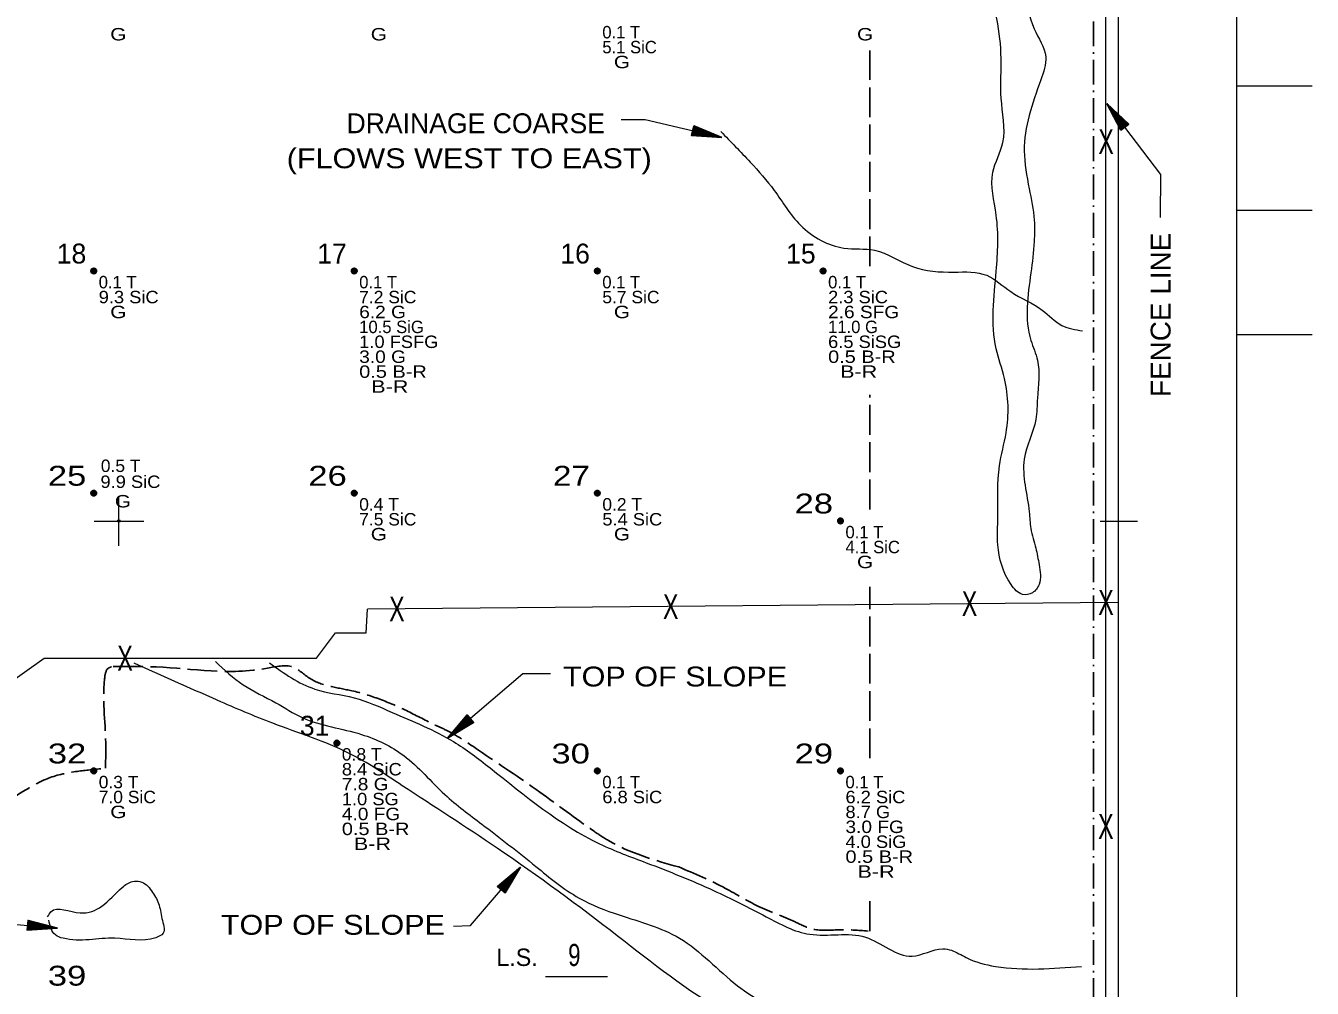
# Model space of a CAD drawing. Extents: x -496 to 480, y -450 to 700.
# Drawn here: x -38 to 480, y -188 to 199 of the extents above; entities that cross this region are included whole.
import ezdxf
from ezdxf.enums import TextEntityAlignment as Align

# ---------------------------------------------------------------- set-up
doc = ezdxf.new("R2010")
doc.units = 0
doc.header["$LTSCALE"] = 2
doc.header["$PDMODE"] = 32
doc.header["$PDSIZE"] = 1
doc.linetypes.add('DOT_DASHED', pattern=[7.7, 5, -1.2, 0.3, -1.2])
doc.linetypes.add('LONG_DASHED', pattern=[7.5, 6, -1.5])
for name, color, linetype, lineweight in [('1', 7, 'Continuous', 13), ('2', 7, 'Continuous', 35), ('3', 7, 'Continuous', 13), ('4', 7, 'Continuous', 25)]:
    doc.layers.add(name, color=color, linetype=linetype, lineweight=lineweight)

msp = doc.modelspace()

# ---------------------------------------------------------------- linework, layer by layer
at = {"layer": '1'}
for p, q in [((402.281, -245.555), (402.281, 402.339)), ((480.331, 174.973), (449.983, 174.973)), ((480.331, 124.973), (449.983, 124.973)), ((480.331, 74.973), (449.983, 74.973)), ((-0.017, -10.027), (-0.017, 9.973)), ((-10.017, -0.027), (9.983, -0.027)), ((394.983, -0.027), (409.983, -0.027)), ((171.67, -183.226), (196.67, -183.226))]:
    msp.add_line(p, q, dxfattribs=at)
msp.add_lwpolyline([(449.983, -450.027), (449.983, 399.973), (449.983, 699.973), (-450.017, 699.973), (-450.017, 49.973), (-450.017, -450.027)], dxfattribs=at)
for p in [(0, 0), (0.001, -0.011)]:
    msp.add_point(p, dxfattribs=at)
at = {"layer": '2', "linetype": 'LONG_DASHED', "lineweight": 25}
for p, q in [((302.281, 102.482), (302.281, 189.292)), ((302.281, 4.688), (302.281, 50.791)), ((302.281, -95.435), (302.281, -26.514)), ((302.281, -164.988), (302.281, -152.715))]:
    msp.add_line(p, q, dxfattribs=at)
at = {"layer": '2'}
for centre in [(-10.129, 100.614), (94.721, 100.614), (192.581, 100.614), (283.451, 100.614), (-10.129, 11.214), (94.721, 11.214), (192.581, 11.214), (290.441, 0.039), (87.731, -89.361), (-10.129, -100.536), (192.581, -100.536), (290.441, -100.536)]:
    msp.add_circle(centre, 1, dxfattribs=at)
for points in [[(-10.14, 101.501), (-9.409, 101.097), (-9.258, 100.248), (-9.943, 99.72), (-10.752, 99.951), (-11.038, 100.709), (-10.791, 101.271), (-10.218, 101.439), (-9.544, 100.945), (-9.561, 100.203), (-10.078, 99.945), (-10.6, 100.114), (-10.825, 100.76), (-10.241, 101.226), (-9.803, 100.692), (-9.842, 100.209), (-10.471, 100.344), (-10.325, 100.979), (-10.033, 100.428)], [(94.71, 101.501), (95.441, 101.097), (95.592, 100.248), (94.907, 99.72), (94.098, 99.951), (93.812, 100.709), (94.059, 101.271), (94.632, 101.439), (95.306, 100.945), (95.289, 100.203), (94.772, 99.945), (94.25, 100.114), (94.025, 100.76), (94.609, 101.226), (95.047, 100.692), (95.008, 100.209), (94.379, 100.344), (94.525, 100.979), (94.817, 100.428)], [(192.57, 101.501), (193.301, 101.097), (193.452, 100.248), (192.767, 99.72), (191.958, 99.951), (191.672, 100.709), (191.919, 101.271), (192.492, 101.439), (193.166, 100.945), (193.149, 100.203), (192.632, 99.945), (192.11, 100.114), (191.885, 100.76), (192.469, 101.226), (192.907, 100.692), (192.868, 100.209), (192.239, 100.344), (192.385, 100.979), (192.677, 100.428)], [(283.44, 101.501), (284.171, 101.097), (284.322, 100.248), (283.637, 99.72), (282.828, 99.951), (282.542, 100.709), (282.789, 101.271), (283.362, 101.439), (284.036, 100.945), (284.019, 100.203), (283.502, 99.945), (282.98, 100.114), (282.755, 100.76), (283.339, 101.226), (283.777, 100.692), (283.738, 100.209), (283.109, 100.344), (283.255, 100.979), (283.547, 100.428)], [(-10.14, 12.101), (-9.409, 11.697), (-9.258, 10.848), (-9.943, 10.32), (-10.752, 10.551), (-11.038, 11.309), (-10.791, 11.871), (-10.218, 12.039), (-9.544, 11.545), (-9.561, 10.803), (-10.078, 10.545), (-10.6, 10.714), (-10.825, 11.36), (-10.241, 11.826), (-9.803, 11.292), (-9.842, 10.809), (-10.471, 10.944), (-10.325, 11.579), (-10.033, 11.028)], [(94.71, 12.101), (95.441, 11.697), (95.592, 10.848), (94.907, 10.32), (94.098, 10.551), (93.812, 11.309), (94.059, 11.871), (94.632, 12.039), (95.306, 11.545), (95.289, 10.803), (94.772, 10.545), (94.25, 10.714), (94.025, 11.36), (94.609, 11.826), (95.047, 11.292), (95.008, 10.809), (94.379, 10.944), (94.525, 11.579), (94.817, 11.028)], [(192.57, 12.101), (193.301, 11.697), (193.452, 10.848), (192.767, 10.32), (191.958, 10.551), (191.672, 11.309), (191.919, 11.871), (192.492, 12.039), (193.166, 11.545), (193.149, 10.803), (192.632, 10.545), (192.11, 10.714), (191.885, 11.36), (192.469, 11.826), (192.907, 11.292), (192.868, 10.809), (192.239, 10.944), (192.385, 11.579), (192.677, 11.028)], [(290.43, 0.926), (291.161, 0.522), (291.312, -0.327), (290.627, -0.855), (289.818, -0.624), (289.532, 0.134), (289.779, 0.696), (290.352, 0.864), (291.026, 0.37), (291.009, -0.372), (290.492, -0.63), (289.97, -0.461), (289.745, 0.185), (290.329, 0.651), (290.767, 0.117), (290.728, -0.366), (290.099, -0.231), (290.245, 0.404), (290.537, -0.147)], [(87.72, -88.474), (88.451, -88.878), (88.602, -89.727), (87.917, -90.255), (87.108, -90.024), (86.822, -89.266), (87.069, -88.704), (87.642, -88.536), (88.316, -89.03), (88.299, -89.772), (87.782, -90.03), (87.26, -89.861), (87.035, -89.215), (87.619, -88.749), (88.057, -89.283), (88.018, -89.766), (87.389, -89.631), (87.535, -88.996), (87.827, -89.547)], [(-10.14, -99.649), (-9.409, -100.053), (-9.258, -100.902), (-9.943, -101.43), (-10.752, -101.199), (-11.038, -100.441), (-10.791, -99.879), (-10.218, -99.711), (-9.544, -100.205), (-9.561, -100.947), (-10.078, -101.205), (-10.6, -101.036), (-10.825, -100.39), (-10.241, -99.924), (-9.803, -100.458), (-9.842, -100.941), (-10.471, -100.806), (-10.325, -100.171), (-10.033, -100.722)], [(192.57, -99.649), (193.301, -100.053), (193.452, -100.902), (192.767, -101.43), (191.958, -101.199), (191.672, -100.441), (191.919, -99.879), (192.492, -99.711), (193.166, -100.205), (193.149, -100.947), (192.632, -101.205), (192.11, -101.036), (191.885, -100.39), (192.469, -99.924), (192.907, -100.458), (192.868, -100.941), (192.239, -100.806), (192.385, -100.171), (192.677, -100.722)], [(290.43, -99.649), (291.161, -100.053), (291.312, -100.902), (290.627, -101.43), (289.818, -101.199), (289.532, -100.441), (289.779, -99.879), (290.352, -99.711), (291.026, -100.205), (291.009, -100.947), (290.492, -101.205), (289.97, -101.036), (289.745, -100.39), (290.329, -99.924), (290.767, -100.458), (290.728, -100.941), (290.099, -100.806), (290.245, -100.171), (290.537, -100.722)]]:
    msp.add_spline(points, degree=3, dxfattribs=at)
at = {"layer": '2', "linetype": 'LONG_DASHED', "lineweight": 25}
for points in [[(-5.46, -99.466), (-5.252, -90.93), (-5.748, -63.446), (-4.261, -59.237), (-2.343, -58.49)], [(-2.343, -58.49), (15.058, -58.715), (59.763, -59.234), (69.9, -58.715), (76.917, -63.388), (84.974, -66.503), (93.811, -68.32), (104.987, -71.695), (116.424, -76.628), (127.34, -82.08), (132.278, -84.416), (144.754, -92.204), (169.445, -109.079), (191.018, -124.655), (196.996, -128.55), (225.326, -139.194)], [(-46.213, -113.44), (-37.202, -108.011), (-28.328, -103.466), (-16.725, -100.739), (-6.714, -99.603), (-5.46, -99.466)], [(225.326, -139.194), (244.199, -147.831), (257.196, -154.935), (272.155, -161.303), (279.512, -164.243), (289.566, -164.488), (301.582, -164.977)]]:
    msp.add_spline(points, degree=3, dxfattribs=at)
at = {"layer": '3'}
for p, q in [((397.281, -246.457), (397.281, 397.339)), ((402.135, -32.826), (100.033, -35.45))]:
    msp.add_line(p, q, dxfattribs=at)
at = {"layer": '3', "linetype": 'DOT_DASHED', "lineweight": 25}
msp.add_line((392.281, 385.802), (392.281, -246.006), dxfattribs=at)
at = {"layer": '3'}
msp.add_lwpolyline([(-418.392, 11.933), (-163.468, 10.85), (-155.332, 0.015), (-122.789, -0.527), (-81.567, -55.245), (-66.922, -55.787), (-66.922, -66.622), (-46.854, -67.164), (-30.04, -55.245), (79.523, -55.245), (87.202, -45.019), (99.497, -44.943), (100.033, -35.45)], dxfattribs=at)
for points in [[(-407.583, 368.504), (-377.691, 369.409), (-355.045, 369.409), (-344.175, 368.504), (-328.776, 371.218), (-313.377, 372.123), (-278.956, 368.504), (-253.593, 366.695), (-220.983, 368.504), (-195.62, 369.409), (-113.189, 371.218), (-62.463, 366.695), (-15.36, 370.314), (129.573, 369.409), (163.088, 366.695), (215.626, 369.409), (283.563, 369.409), (313.456, 370.314), (344.254, 369.409), (357.841, 369.409), (358.747, 364.885), (359.653, 358.552), (346.971, 354.028), (317.985, 355.837), (282.658, 358.552), (167.617, 358.552), (86.999, 357.647), (29.026, 354.028), (-29.853, 357.647), (-94.167, 358.552), (-118.624, 356.742), (-177.503, 359.456), (-248.158, 354.932), (-325.153, 358.552), (-355.951, 354.932), (-383.126, 358.552), (-389.467, 354.932), (-393.996, 342.265), (-393.09, 244.549), (-392.184, 178.5), (-393.996, 113.356), (-393.996, 88.927), (-393.09, 59.974), (-392.184, 33.736), (-397.619, 15.64), (-404.866, 15.64), (-411.207, 31.021), (-407.583, 90.737), (-410.301, 145.024), (-408.489, 188.453), (-408.489, 262.645), (-411.207, 278.931), (-407.583, 312.408), (-409.395, 347.694), (-409.395, 353.123), (-415.736, 357.647)], [(353.782, 336.707), (359.096, 341.351), (366.402, 339.361), (369.059, 331.4), (366.402, 320.121), (367.731, 310.833), (365.738, 297.564), (366.402, 288.94), (367.066, 284.296), (367.066, 273.017), (369.059, 262.402), (369.059, 251.787), (367.066, 239.846), (364.41, 233.875), (364.41, 227.904), (368.395, 198.049), (373.044, 186.771), (371.052, 177.483), (364.41, 148.955), (366.402, 133.696), (368.395, 121.091), (368.395, 112.466), (367.066, 99.861), (367.066, 72.66), (369.723, 64.699), (369.723, 49.44), (369.059, 40.815), (364.41, 24.893), (366.402, 3.663), (367.066, -2.971), (369.059, -10.932), (370.387, -17.567), (370.387, -25.528), (367.731, -28.845), (363.745, -29.509), (359.096, -25.528), (353.782, -9.606), (353.782, 1.673), (354.447, 22.239), (357.103, 35.508), (356.439, 57.401), (353.118, 69.343), (353.118, 100.524), (353.118, 123.081), (351.79, 140.331), (355.775, 152.272), (355.111, 170.185), (355.111, 184.117), (353.782, 200.04), (350.461, 221.933), (353.118, 238.519), (355.775, 253.114), (355.111, 274.344), (353.118, 294.247), (351.125, 313.487), (350.461, 322.775), (351.79, 332.063), (354.447, 338.697)], [(242.275, 156.692), (254.119, 144.424), (263.769, 133.033), (274.297, 119.012), (282.631, 112.878), (291.842, 109.811), (304.125, 108.935), (319.477, 102.363), (336.146, 100.172), (349.305, 98.858), (358.955, 92.286), (371.676, 84.837), (379.572, 78.703), (387.906, 76.513)], [(38.939, -56.557), (49.996, -65.901), (63.179, -73.122), (73.81, -79.069), (97.624, -85.865), (114.634, -94.36), (131.219, -110.076), (146.103, -121.97), (167.791, -138.96), (185.226, -151.703), (201.386, -158.499), (225.625, -167.844), (249.014, -186.958), (260.496, -194.604), (267.3, -199.276), (275.38, -208.196), (281.758, -211.169), (291.16, -212.829)], [(237.229, -257.097), (233.19, -252.437), (217.369, -252.437), (203.408, -246.859), (199.685, -239.422), (195.963, -231.985), (201.547, -229.197), (211.784, -235.704), (240.636, -237.563), (254.596, -236.633), (262.042, -230.126), (263.903, -214.323), (245.289, -198.519), (200.616, -166.912), (152.22, -131.587), (114.062, -106.488), (92.656, -93.473), (61.943, -81.388), (39.607, -72.092), (6.102, -57.218)], [(60.597, -57.041), (78.822, -67.611), (94.695, -71.134), (109.98, -77.006), (134.671, -88.75), (149.368, -99.32), (193.46, -129.855), (212.273, -137.489), (239.315, -148.646), (260.479, -159.215), (278.116, -166.262), (300.456, -167.436), (309.862, -172.134), (319.268, -175.07), (331.614, -172.134), (335.141, -172.721), (341.02, -175.657), (352.778, -179.18), (387.464, -179.18)], [(-28.687, -159.22), (-27.354, -157.223), (-15.577, -157.667), (-6.912, -155.003), (1.309, -147.458), (5.531, -145.016), (11.086, -146.348), (13.086, -148.789), (15.974, -153.894), (17.308, -159.886), (17.752, -165.878), (14.863, -167.654), (-1.579, -167.876), (-22.465, -167.876), (-25.576, -166.544), (-28.242, -160.552)]]:
    msp.add_spline(points, degree=3, dxfattribs=at)
at = {"layer": '4', "lineweight": 13}
for points in [[(419.287, 122.176), (419.425, 139.363), (397.64, 168.053)], [(202.101, 161.518), (211.806, 161.518), (242.654, 154.248)], [(173.732, -61.419), (162.605, -61.419), (132.313, -87.353)], [(134.713, -163.058), (141.529, -162.775), (161.694, -139.229)], [(-80.976, -159.656), (-71.087, -159.656), (-24.776, -163.751)]]:
    msp.add_lwpolyline(points, dxfattribs=at)
at = {"layer": '4'}
for points in [[(397.64, 168.053), (403.304, 157.286), (406.49, 159.705)], [(242.654, 154.248), (231.433, 158.947), (230.515, 155.054)], [(132.313, -87.353), (142.73, -81.068), (140.128, -78.029)], [(161.694, -139.229), (152.369, -147.043), (155.407, -149.645)], [(-24.776, -163.751), (-36.554, -160.702), (-36.906, -164.686)]]:
    msp.add_lwpolyline(points, close=True, dxfattribs=at)
for points in [[(403.339, 157.436), (397.987, 167.595), (406.261, 159.735), (403.451, 157.576), (398.432, 167.008), (406.007, 159.787), (403.467, 157.803), (398.903, 166.389), (405.716, 159.81), (403.56, 158.037), (399.421, 165.672), (405.416, 159.882), (403.602, 158.342), (400.044, 164.812), (405.092, 159.88), (403.679, 158.67), (400.719, 163.889), (404.664, 159.907), (403.71, 159.02), (401.427, 162.85), (404.249, 160.025), (403.72, 159.435), (402.346, 161.674), (403.722, 160.114)], [(231.501, 158.809), (242.096, 154.38), (230.712, 155.176), (231.504, 158.63), (241.379, 154.549), (230.94, 155.298), (231.636, 158.444), (240.621, 154.728), (231.179, 155.466), (231.713, 158.205), (239.765, 154.951), (231.457, 155.6), (231.875, 157.943), (238.738, 155.217), (231.705, 155.808), (232.025, 157.641), (237.629, 155.5), (232.052, 156.06), (232.224, 157.352), (236.422, 155.851), (232.448, 156.233), (232.48, 157.025), (234.965, 156.173), (232.91, 156.5)], [(142.578, -81.041), (132.75, -86.98), (140.111, -78.26), (142.432, -80.938), (133.309, -86.501), (140.075, -78.516), (142.204, -80.935), (133.9, -85.995), (140.069, -78.808), (141.965, -80.856), (134.586, -85.435), (140.014, -79.111), (141.658, -80.832), (135.407, -84.763), (140.035, -79.435), (141.326, -80.775), (136.29, -84.035), (140.033, -79.863), (140.975, -80.764), (137.286, -83.268), (139.94, -80.285), (140.56, -80.778), (138.405, -82.282), (139.882, -80.816)], [(152.523, -147.045), (161.32, -139.665), (155.389, -149.414), (152.684, -147.125), (160.841, -140.224), (155.385, -149.155), (152.909, -147.093), (160.335, -140.815), (155.346, -148.866), (153.157, -147.134), (159.744, -141.474), (155.354, -148.558), (153.464, -147.111), (159.036, -142.264), (155.283, -148.241), (153.801, -147.116), (158.276, -143.12), (155.219, -147.818), (154.15, -147.072), (157.41, -144.031), (155.246, -147.387), (154.557, -146.995), (156.455, -145.178), (155.222, -146.853)], [(-36.466, -160.829), (-25.348, -163.7), (-36.729, -164.537), (-36.438, -161.006), (-26.082, -163.635), (-36.52, -164.384), (-36.281, -161.171), (-26.857, -163.567), (-36.308, -164.184), (-36.17, -161.397), (-27.736, -163.468), (-36.053, -164.011), (-35.972, -161.633), (-28.791, -163.351), (-35.836, -163.77), (-35.781, -161.91), (-29.929, -163.23), (-35.528, -163.472), (-35.543, -162.168), (-31.174, -163.055), (-35.162, -163.244), (-35.243, -162.455), (-32.661, -162.944), (-34.742, -162.913)]]:
    msp.add_lwpolyline(points, dxfattribs=at)

# ---------------------------------------------------------------- texts
at = {"layer": '1', "width": 0.75}
msp.add_text('9', height=8.89, dxfattribs=at).set_placement((183.312, -179.052), align=Align.CENTER)
at = {"layer": '1'}
msp.add_text('L.S.', height=7, dxfattribs=at).set_placement((160.254, -179.023), align=Align.CENTER)
at = {"layer": '2'}
for s, width, p in [('  G        ', 1.25, (-8.129, 193.364)), ('  G        ', 1.25, (96.721, 193.364)), ('  G        ', 1.25, (292.441, 193.364)), ('  G        ', 1.25, (194.581, 182.189)), ('9.3 SiC    ', 1.1, (-8.129, 87.614)), ('7.2 SiC    ', 1.05, (96.721, 87.614)), ('5.7 SiC    ', 1.05, (194.581, 87.614)), ('2.3 SiC    ', 1.1, (285.451, 87.614)), ('  G        ', 1.25, (-8.129, 81.614)), ('6.2 G      ', 1.15, (96.721, 81.614)), ('  G        ', 1.25, (194.581, 81.614)), ('2.6 SFG    ', 1.15, (285.451, 81.614)), ('1.0 FSFG   ', 1.1, (96.721, 69.614)), ('6.5 SiSG   ', 1.1, (285.451, 69.614)), ('3.0 G      ', 1.15, (96.721, 63.614)), ('0.5 B-R    ', 1.2, (285.451, 63.614)), ('0.5 B-R    ', 1.2, (96.721, 57.614)), ('  B-R      ', 1.3, (285.451, 57.614)), ('  B-R      ', 1.3, (96.721, 51.614)), ('0.5 T      ', 1.05, (-7.282, 19.724)), ('9.9 SiC    ', 1.1, (-7.423, 13.302)), ('  G        ', 1.25, (-6.294, 5.468)), ('0.4 T      ', 1.05, (96.721, 4.214)), ('0.2 T      ', 1.05, (194.581, 4.214)), ('7.5 SiC    ', 1.05, (96.721, -1.786)), ('5.4 SiC    ', 1.1, (194.581, -1.786)), ('  G        ', 1.25, (96.721, -7.786)), ('  G        ', 1.25, (194.581, -7.786)), ('  G        ', 1.25, (292.441, -18.961)), ('0.8 T      ', 1.05, (89.731, -96.361)), ('8.4 SiC    ', 1.1, (89.731, -102.361)), ('0.3 T      ', 1.05, (-8.129, -107.536)), ('7.8 G      ', 1.15, (89.731, -108.361)), ('7.0 SiC    ', 1.05, (-8.129, -113.536)), ('6.8 SiC    ', 1.1, (194.581, -113.536)), ('6.2 SiC    ', 1.1, (292.441, -113.536)), ('1.0 SG     ', 1.1, (89.731, -114.361)), ('  G        ', 1.25, (-8.129, -119.536)), ('4.0 FG     ', 1.15, (89.731, -120.361)), ('8.7 G      ', 1.1, (292.441, -119.536)), ('0.5 B-R    ', 1.2, (89.731, -126.361)), ('3.0 FG     ', 1.15, (292.441, -125.536)), ('  B-R      ', 1.3, (89.731, -132.361)), ('4.0 SiG    ', 1.1, (292.441, -131.536)), ('0.5 B-R    ', 1.2, (292.441, -137.536)), ('  B-R      ', 1.3, (292.441, -143.536))]:
    msp.add_text(s, height=5, dxfattribs=dict(at, width=width)).set_placement(p)
for s, p in [('0.1 T      ', (194.581, 194.189)), ('5.1 SiC    ', (194.581, 188.189)), ('0.1 T      ', (-8.129, 93.614)), ('0.1 T      ', (96.721, 93.614)), ('0.1 T      ', (194.581, 93.614)), ('0.1 T      ', (285.451, 93.614)), ('10.5 SiG   ', (96.721, 75.614)), ('11.0 G     ', (285.451, 75.614)), ('0.1 T      ', (292.441, -6.961)), ('4.1 SiC    ', (292.441, -12.961)), ('0.1 T      ', (194.581, -107.536)), ('0.1 T      ', (292.441, -107.536))]:
    msp.add_text(s, height=5, dxfattribs=at).set_placement(p)
for s, p in [(' 18', (-13.129, 103.614)), (' 17', (91.721, 103.614)), (' 16', (189.581, 103.614)), (' 15', (280.451, 103.614)), (' 31', (84.731, -86.361))]:
    msp.add_text(s, height=8, dxfattribs=at).set_placement(p, align=Align.RIGHT)
for s, width, p in [(' 25', 1.3, (-13.129, 14.214)), (' 26', 1.3, (91.721, 14.214)), (' 27', 1.25, (189.581, 14.214)), (' 28', 1.3, (287.441, 3.039)), (' 32', 1.3, (-13.129, -97.536)), (' 30', 1.3, (189.581, -97.536)), (' 29', 1.3, (287.441, -97.536)), (' 39', 1.3, (-13.129, -186.936))]:
    msp.add_text(s, height=8, dxfattribs=dict(at, width=width)).set_placement(p, align=Align.RIGHT)
at = {"layer": '3', "width": 0.7}
for p in [(397.338, 147.663), (111.893, -40.418), (222.099, -39.44), (342.378, -38.222), (397.293, -37.75), (2.475, -60.171), (397.253, -127.917)]:
    msp.add_text('X', height=10, dxfattribs=at).set_placement(p, align=Align.CENTER)
at = {"layer": '4'}
msp.add_text('DRAINAGE COARSE', height=8, dxfattribs=at).set_placement((143.628, 156.037), align=Align.CENTER)
at = {"layer": '4', "width": 1.15}
for s, p in [('(FLOWS WEST TO EAST)', (141.012, 141.946)), ('TOP OF SLOPE', (223.839, -66.567)), ('TOP OF SLOPE', (86.144, -166.471))]:
    msp.add_text(s, height=8, dxfattribs=at).set_placement(p, align=Align.CENTER)
at = {"layer": '4', "width": 1.05}
msp.add_text('FENCE LINE', height=8, rotation=90, dxfattribs=at).set_placement((423.297, 82.95), align=Align.CENTER)

doc.saveas('drawing.dxf')
